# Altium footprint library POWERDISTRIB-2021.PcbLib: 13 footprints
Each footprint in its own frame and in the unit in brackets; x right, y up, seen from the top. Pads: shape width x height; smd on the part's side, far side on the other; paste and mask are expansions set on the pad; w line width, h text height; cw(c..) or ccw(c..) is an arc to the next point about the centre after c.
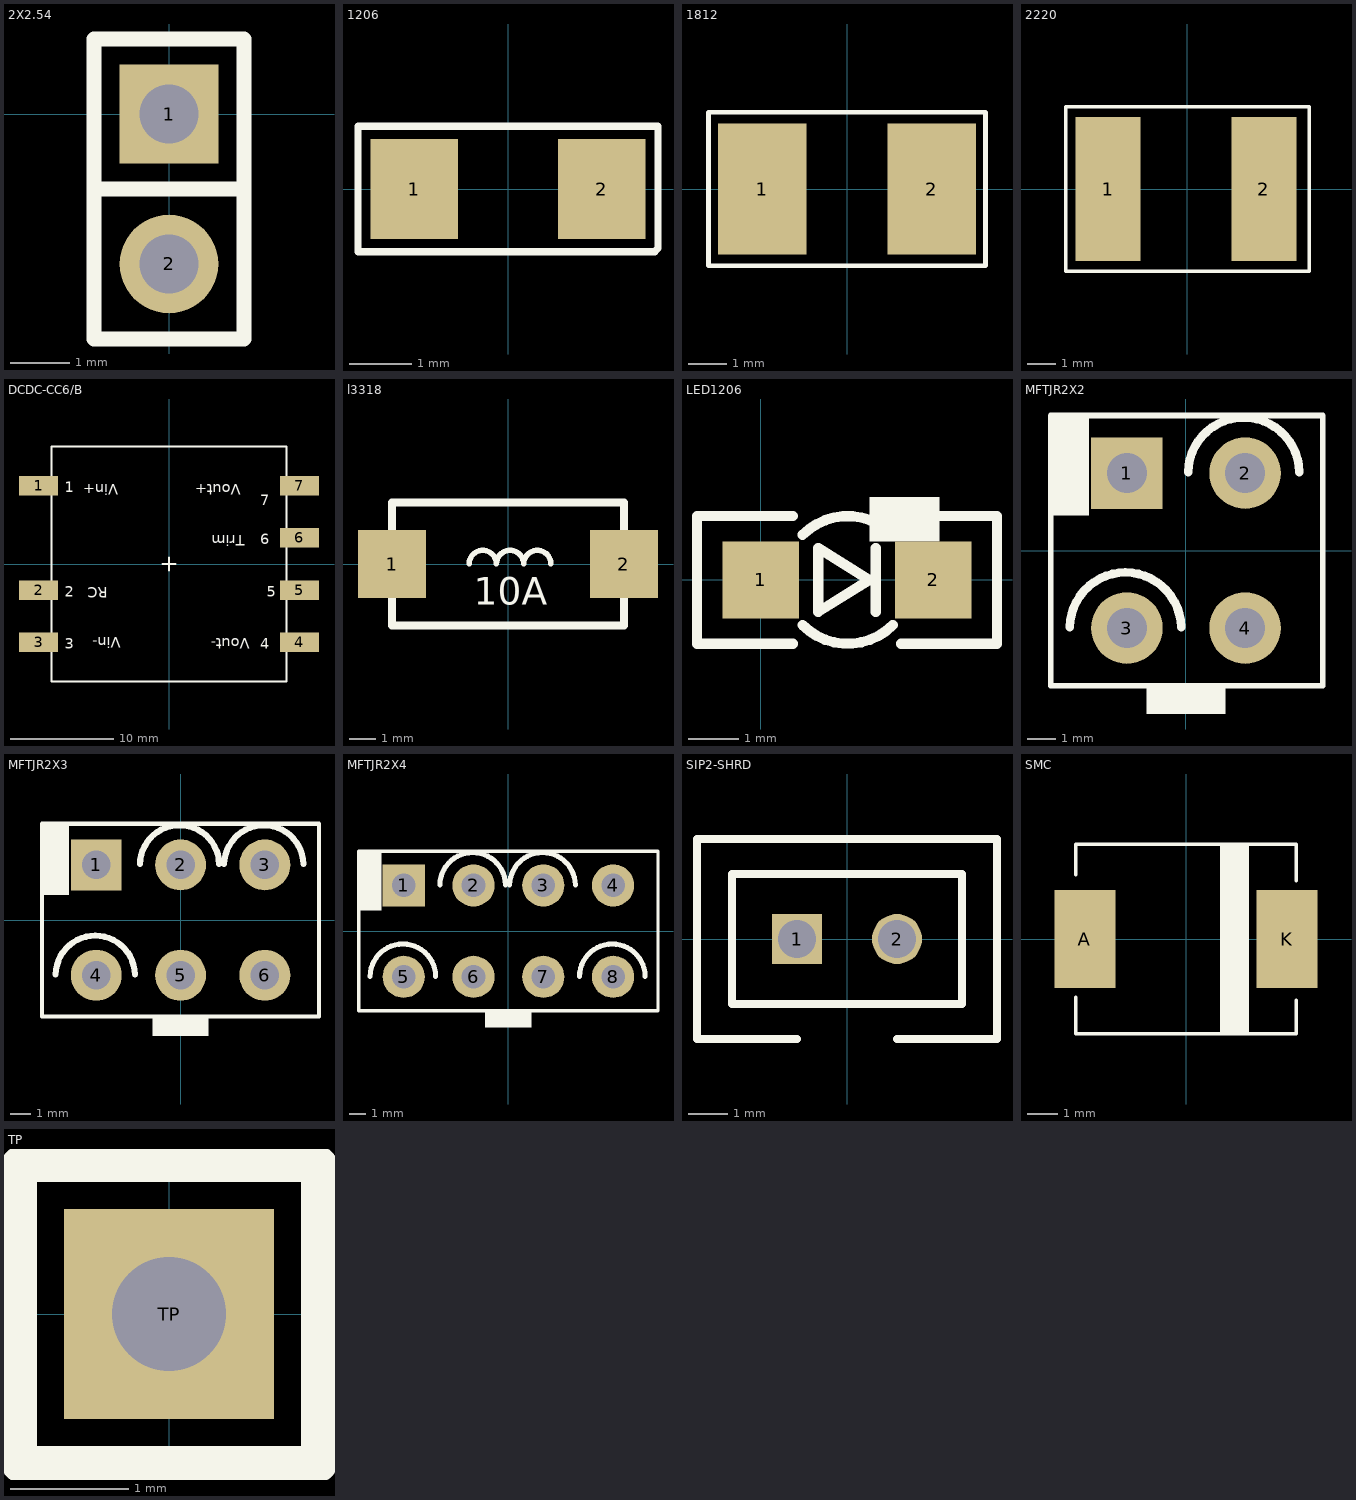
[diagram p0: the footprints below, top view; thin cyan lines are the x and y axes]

## 2X2.54 [mm]
height 4.27
pads (2):
  rect 1.67x1.67 hole 1: 1(0,0)
  round 1.67 hole 1: 2(0,-2.54)
Top Overlay:
  lines w0.254: -1.27,1.27 -1.27,-3.81 1.27,-3.81 1.27,1.27 ; -1.27,1.27 1.27,1.27 ; -1.27,1.27 -1.27,-1.27 1.27,-1.27 1.27,1.27 ; -1.27,1.27 1.27,1.27
3D body "215398_A60-02-7-G-.stp": height 9.54, standoff -3, extent -1.257,-3.797 1.283,1.283

## 1206 [mm]
pads (2):
  rect 1.4x1.6 smd mask+0.05: 1(-1.5,0) 2(1.5,0)
Top Overlay:
  lines w0.12: -2.4,-1 2.35,-1 2.4,-0.95 2.4,0.95 2.4,1 -2.4,1 -2.4,-1
3D body "User Library-1206 SMD Resistor.step": height 1, standoff 0, extent -1.6,-0.8 1.6,0.8

## 1812 [mm]
pads (2):
  rect 2.3x3.4 smd: 1(-2.2,0) 2(2.2,0)
Top Overlay:
  lines w0.12: -3.6,-2 3.6,-2 3.6,2 -3.4,2 -3.6,2 -3.6,-2
3D body "SW3dPS-1812 SMD Capacitor.STEP": height 1.6, standoff 0, extent -2.25,-1.597 2.25,1.603

## 2220 [mm]
pads (2):
  rect 2.3x5.1 smd: 1(-2.8,0) 2(2.7,0)
Top Overlay:
  lines w0.12: -4.3,-2.9 4.3,-2.9 4.3,2.9 -4.3,2.9 -4.3,-2.9
3D body "2220.STEP": height 2.3, standoff 0, extent -2.856,-2.527 2.844,2.473

## DCDC-CC6/B [mil]
height 168.11
pads (7):
  rect 150x75 smd: 1(-500,300) 2(-500,-100) 3(-500,-300) 4(500,-300) 5(500,-100) 6(500,100) 7(500,300)
Top Overlay:
  lines w8: -25,0 25,0 ; 0,-25 0,25 ; -450,-450 -450,450 450,450 450,-450 -450,-450
  text "Vin+" at -195,305 h40
  text "Vout+" at 275,305 h40
  text "Trim" at 290,110 h40
  text "RC" at -235,-90 h40
  text "Vin-" at -185,-280 h40
  text "Vout-" at 310,-285 h40
  text "2" at -400,-125 h40
  text "3" at -400,-325 h40
  text "1" at -400,275 h40
  text "4" at 350,-325 h40
  text "5" at 375,-125 h40
  text "6" at 350,75 h40
  text "7" at 350,225 h40
Top Paste:
  region: -430,335 -570,335 -570,265 -430,265
  region: -430,-65 -570,-65 -570,-135 -430,-135
  region: -430,-270 -565,-270 -565,-335 -430,-335
  region: 570,-265 430,-265 430,-335 570,-335
  region: 570,-70 430,-70 430,-135 570,-135
  region: 565,135 435,135 435,65 565,65
  region: 565,335 435,335 435,270 565,270
Mechanical 1:
  text "DCDC-CC6" at 435,-385 h40
  text "CC6-xxyySR-E" at 190,425 h40
3D body "cc6-r-e_outline.STEP": height 346.46, standoff 0, extent -515,-415.35 514.92,415.35

## l3318 [mil]
pads (2):
  rect 100x100 smd: 1(-170,0) 2(170,0)
Top Overlay:
  lines w8: -57,0 cw(c-37,0) -17,0 cw(c3,0) 23,0 cw(c43,0) 63,0
  lines w12: -170,-90 170,-90 170,90 -170,90 -170,-90
  text "10A" at -50,-60 h40
Top Paste:
  region: -125,45 -215,45 -215,-45 -125,-45
  region: 215,45 125,45 125,-45 215,-45
Mechanical 1:
  text "240-2511-1-ND" at -230,60 h40

## LED1206 [mil]
height 168.11
pads (2):
  rect 60x60 smd: 1(0,0) 2(135,0)
Top Overlay:
  region: 85,65 85,30 140,30 140,65
  lines w8: 25,-50 -50,-50 -50,50 25,50 ; 32.64,-35.36 ccw(c68,0) 103.36,-35.36 ; 32.64,35.36 cw(c68,0) 103.36,35.36 ; 90,-25 90,25 ; 110,-50 185,-50 185,50 110,50 ; 45,-25 85,0 45,25 45,-25

## MFTJR2X2 [mm]
height 4.27
pads (4):
  rect 2.54x2.54 hole 1.422: 1(-2.1,2.75)
  round 2.54 hole 1.422: 2(2.1,2.75) 3(-2.1,-2.75) 4(2.1,-2.75)
Top Overlay:
  region: -3.45,4.85 -4.85,4.85 -4.85,1.25 -3.45,1.25
  region: 1.4,-4.8 -1.4,-4.8 -1.4,-5.8 1.4,-5.8
  lines w0.203: -4.8,-4.8 4.85,-4.8 4.85,4.8 -4.8,4.8 -4.8,-4.8
  lines w0.305: -4.125,-2.716 cw(c-2.15,-2.75) -0.175,-2.716 ; 0.075,2.784 cw(c2.05,2.75) 4.025,2.784
Mechanical 1:
  text "WM3801-ND" at -4.3,-1.275 h1
  text "MFTJR2X2" at -4.125,0.025 h1
3D body "039281043.stp": height 12.8, standoff -3.5, extent -5.2,-6.073 5.2,4.927

## MFTJR2X3 [mm]
pads (6):
  rect 2.54x2.54 hole 1.422: 1(-4.2,2.75)
  round 2.54 hole 1.422: 2(0,2.75) 3(4.2,2.75) 4(-4.2,-2.75) 5(0,-2.75) 6(4.2,-2.75)
Top Overlay:
  region: 1.4,-5.788 1.4,-4.788 -1.4,-4.788 -1.4,-5.788
  region: -5.55,1.25 -5.55,4.85 -6.95,4.85 -6.95,1.25
  lines w0.203: -6.9,-4.8 -6.9,4.8 6.9,4.8 6.9,-4.8 -6.9,-4.8
  lines w0.305: -6.225,-2.716 cw(c-4.25,-2.75) -2.275,-2.716 ; -2.025,2.784 cw(c-0.05,2.75) 1.925,2.784 ; 2.175,2.784 cw(c4.15,2.75) 6.125,2.784
Mechanical 1:
  text "MFTJR2X3" at -3.375,0.3 h1.02
  text "WM3802-ND" at -4.575,-1.4 h1.27
3D body "039281063.stp": height 12.8, standoff -3.5, extent -7.3,-5.92 7.3,5.08

## MFTJR2X4 [mm]
height 4.27
pads (8):
  rect 2.54x2.54 hole 1.422: 1(-6.3,2.75)
  round 2.54 hole 1.422: 2(-2.1,2.75) 3(2.1,2.75) 4(6.3,2.75) 5(-6.3,-2.75) 6(-2.1,-2.75) 7(2.1,-2.75) 8(6.3,-2.75)
Top Overlay:
  region: 1.4,-4.8 -1.4,-4.8 -1.4,-5.8 1.4,-5.8
  region: -7.65,4.85 -9.05,4.85 -9.05,1.25 -7.65,1.25
  lines w0.203: -9,-4.8 -9,4.8 9,4.8 9,-4.8 -9,-4.8
  lines w0.305: -8.325,-2.716 cw(c-6.35,-2.75) -4.375,-2.716 ; -4.125,2.784 cw(c-2.15,2.75) -0.175,2.784 ; 0.075,2.784 cw(c2.05,2.75) 4.025,2.784 ; 4.275,-2.716 cw(c6.25,-2.75) 8.225,-2.716
Mechanical 1:
  text "MFTJR2X4" at -3.95,0.2 h1.02
  text "WM3803-ND" at -5.75,-1.35 h1.27
3D body "039281083.stp": height 12.8, standoff -3.5, extent -9.4,-6.2 9.4,4.8

## SIP2-SHRD [mil]
height 168.11
pads (2):
  rect 50x50 hole 38: 1(-50,0)
  round 50 hole 38: 2(50,0)
Top Overlay:
  lines w8: -50,-100 -150,-100 -150,100 150,100 150,-100 50,-100 ; -115,-65 -115,65 115,65 115,-65 -115,-65

## SMC [mm]
pads (2):
  rect 2x3.2 smd: A(-3.304,0) K(3.304,0)
Top Overlay:
  rectangle: 1.111,-3.1 2.064,3.1
  lines w0.12: -3.6,-1.9 -3.6,-3.1 3.6,-3.1 3.6,-2 ; -3.6,2.1 -3.6,3.1 3.6,3.1 3.6,1.9
3D body "User Library-DO-214AB(SMC).STEP": height 2.62, standoff -0.02, extent -4.045,-3.131 4.083,3.168

## TP [mil]
height 168.11
pads (1):
  rect 70x70 hole 38: TP(0,0)
Top Overlay:
  lines w12: -50,-50 50,-50 50,50 -50,50 -50,-50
